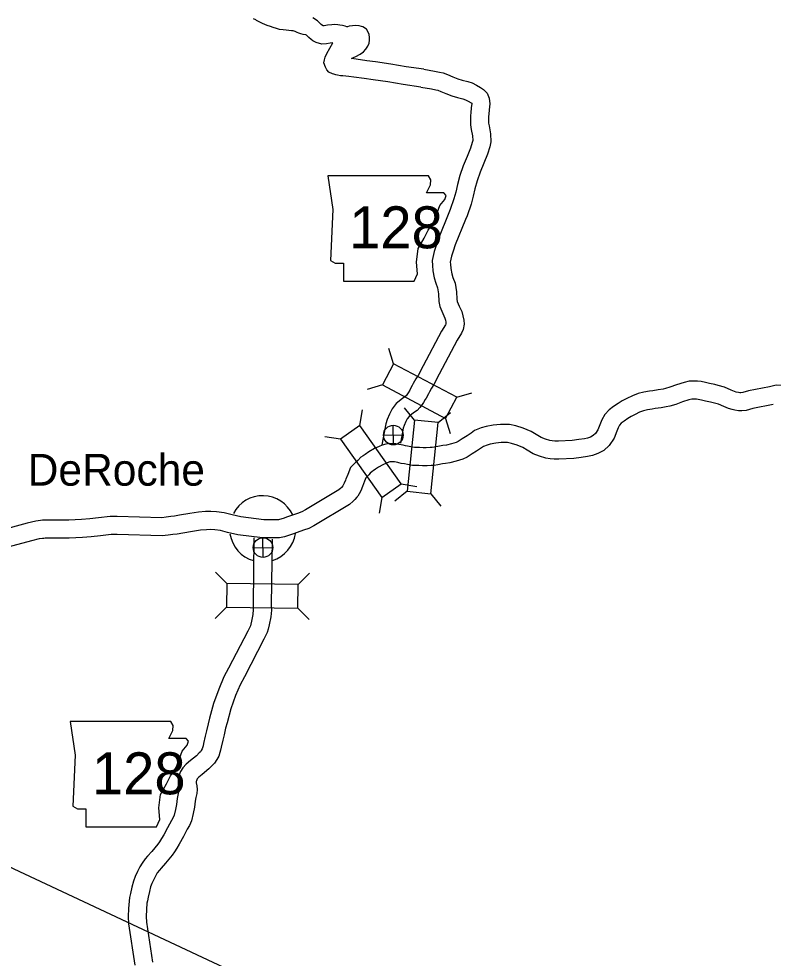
# Model space of a CAD drawing. Extents: x 1373862 to 1377080, y 1164775 to 1170415.
# Drawn here: x 1374284.4 to 1374409.6, y 1170151.1 to 1170307.2 of the extents above; entities that cross this region are included whole.
import ezdxf

# ---------------------------------------------------------------- set-up
doc = ezdxf.new("R2010")
doc.units = 0
doc.layers.add('1', color=7, linetype='Continuous')
doc.layers.add('Default', color=7, linetype='Continuous')

msp = doc.modelspace()

# ---------------------------------------------------------------- linework, layer by layer
at = {"layer": '1'}
msp.add_line((1374155.09, 1170226.04), (1374640.76, 1169998.76), dxfattribs=at)
at = {"layer": 'Default'}
for p, q in [((1374346.6, 1170249.86), (1374345.83, 1170252.38)), ((1374344.75, 1170246.36), (1374342.22, 1170245.59)), ((1374357.1, 1170244.29), (1374359.62, 1170245.06)), ((1374340.99, 1170239.6), (1374341.43, 1170242.21)), ((1374350.09, 1170240.49), (1374348.43, 1170242.54)), ((1374354.03, 1170240.08), (1374356.08, 1170241.75)), ((1374355.24, 1170240.79), (1374356.01, 1170238.27)), ((1374346.6, 1170236.39), (1374346.52, 1170239.64)), ((1374337.76, 1170237.31), (1374335.16, 1170237.75)), ((1374344.93, 1170237.98), (1374348.19, 1170238.05)), ((1374347.88, 1170229.93), (1374350.48, 1170229.49)), ((1374348.86, 1170228.68), (1374346.82, 1170227.01)), ((1374352.8, 1170228.27), (1374354.47, 1170226.22)), ((1374344.65, 1170227.63), (1374344.21, 1170225.03)), ((1374324.95, 1170217.69), (1374324.88, 1170220.95)), ((1374323.29, 1170219.28), (1374326.54, 1170219.36)), ((1374318.89, 1170213.36), (1374317.05, 1170215.25)), ((1374330.77, 1170213.21), (1374332.66, 1170215.06)), ((1374318.85, 1170209.4), (1374316.96, 1170207.55)), ((1374330.72, 1170209.25), (1374332.57, 1170207.36))]:
    msp.add_line(p, q, dxfattribs=at)
for points in [[(1374351.15, 1170295.83), (1374348.22, 1170296.24), (1374345.66, 1170296.7), (1374343.19, 1170297.05), (1374341.72, 1170297.25), (1374340, 1170297.51), (1374339.15, 1170297.61), (1374338.15, 1170297.72), (1374337.78, 1170297.73), (1374337.31, 1170297.8), (1374337, 1170297.86), (1374336.7, 1170297.96), (1374336.45, 1170298.02), (1374335.84, 1170298.33), (1374335.51, 1170298.72), (1374335.27, 1170299.14), (1374335.04, 1170299.85), (1374335.15, 1170300.38), (1374335.23, 1170300.78), (1374335.53, 1170301.42), (1374336.54, 1170303.19), (1374336.06, 1170303.13), (1374335.44, 1170303.02), (1374334.67, 1170302.96), (1374333.73, 1170303.24), (1374333.2, 1170303.53), (1374332.89, 1170303.76), (1374332.55, 1170304.05), (1374332.31, 1170304.29), (1374332.15, 1170304.44), (1374332.05, 1170304.5), (1374331.6, 1170304.57), (1374331.18, 1170304.68), (1374330.89, 1170304.77), (1374330.57, 1170304.93), (1374330.38, 1170305.03), (1374330.27, 1170305.07), (1374330.08, 1170305.13), (1374329.93, 1170305.16), (1374329.67, 1170305.19), (1374329.19, 1170305.23), (1374328.75, 1170305.31), (1374328.29, 1170305.35), (1374327.64, 1170305.43), (1374327.16, 1170305.55), (1374326.62, 1170305.74), (1374326.16, 1170305.88), (1374325.62, 1170306.06), (1374324.86, 1170306.39), (1374324.4, 1170306.6), (1374323.83, 1170306.91), (1374323.7, 1170307), (1374323.35, 1170307.18)], [(1374351.62, 1170298.79), (1374348.69, 1170299.21), (1374346.14, 1170299.66), (1374343.6, 1170300.03), (1374342.14, 1170300.22), (1374340.4, 1170300.49), (1374339.64, 1170300.57), (1374339.81, 1170300.67), (1374340.04, 1170300.83), (1374340.36, 1170300.94), (1374341.04, 1170301.3), (1374341.61, 1170301.71), (1374342.02, 1170302.13), (1374342.33, 1170302.65), (1374342.53, 1170303.13), (1374342.62, 1170303.65), (1374342.62, 1170304.1), (1374342.55, 1170304.56), (1374342.36, 1170304.96), (1374342.08, 1170305.44), (1374341.48, 1170305.83), (1374341.25, 1170305.88), (1374340.9, 1170306.02), (1374340.26, 1170306.08), (1374339.77, 1170306.03), (1374339.21, 1170305.93), (1374338.96, 1170305.86), (1374338.94, 1170305.86), (1374338.93, 1170305.86), (1374338.85, 1170305.87), (1374338.58, 1170305.95), (1374338.1, 1170306.06), (1374337.68, 1170306.11), (1374337.33, 1170306.16), (1374336.86, 1170306.21), (1374336.35, 1170306.19), (1374335.61, 1170306.1), (1374335.05, 1170306), (1374334.99, 1170305.99), (1374334.88, 1170306.02), (1374334.83, 1170306.05), (1374334.78, 1170306.09), (1374334.59, 1170306.26), (1374334.37, 1170306.47), (1374333.95, 1170306.86), (1374333.19, 1170307.32)], [(1374351.62, 1170298.79), (1374353.41, 1170298.48), (1374354.24, 1170298.33), (1374354.85, 1170298.18), (1374355.57, 1170297.91), (1374356.46, 1170297.53), (1374357.26, 1170297.2), (1374358.02, 1170296.99), (1374358.94, 1170296.75), (1374359.65, 1170296.52), (1374360.4, 1170296.17), (1374361.06, 1170295.78), (1374361.55, 1170295.45), (1374362.17, 1170294.82), (1374362.5, 1170294), (1374362.61, 1170293.07), (1374362.47, 1170292.08), (1374362.42, 1170291.35), (1374362.39, 1170290.95), (1374362.36, 1170290.37), (1374362.36, 1170289.85), (1374362.46, 1170289.37), (1374362.7, 1170288.09), (1374362.75, 1170286.72), (1374362.57, 1170285.89), (1374362.2, 1170284.67), (1374361.6, 1170283.17), (1374360.98, 1170281.68), (1374360.49, 1170280.24), (1374360.1, 1170278.91), (1374359.83, 1170277.7), (1374359.48, 1170276.38), (1374358.81, 1170274.44), (1374358.57, 1170273.83), (1374356.85, 1170269.6), (1374356.5, 1170268.59), (1374356.23, 1170267.73), (1374356.02, 1170266.77), (1374356.05, 1170266.43), (1374356.12, 1170265.72), (1374356.27, 1170264.82), (1374356.46, 1170264.19), (1374356.81, 1170263.25), (1374357.03, 1170261.81), (1374357.1, 1170260.58), (1374357.16, 1170260.22), (1374357.5, 1170259.42), (1374357.91, 1170258.53), (1374358.13, 1170257.85), (1374358.28, 1170257.13), (1374358.3, 1170256.45), (1374358.15, 1170255.55), (1374357.87, 1170254.93), (1374357.16, 1170253.79), (1374354.18, 1170248.12), (1374353.27, 1170246.44), (1374352.9, 1170245.82), (1374352.54, 1170245.19), (1374352.39, 1170244.88), (1374351.99, 1170244.14), (1374351.87, 1170243.94), (1374351.58, 1170243.44), (1374351.34, 1170243.09), (1374350.95, 1170242.58), (1374350.5, 1170242.12), (1374349.91, 1170241.7), (1374349.17, 1170241.12), (1374348.87, 1170240.74), (1374348.64, 1170240.28), (1374348.37, 1170239.6), (1374348.22, 1170239.14), (1374347.74, 1170236.65)], [(1374351.15, 1170295.83), (1374352.9, 1170295.52), (1374353.63, 1170295.4), (1374353.95, 1170295.32), (1374354.46, 1170295.12), (1374355.3, 1170294.77), (1374356.27, 1170294.36), (1374357.24, 1170294.09), (1374358.11, 1170293.86), (1374358.55, 1170293.72), (1374359.01, 1170293.51), (1374359.47, 1170293.24), (1374359.58, 1170293.17), (1374359.59, 1170293.1), (1374359.48, 1170292.39), (1374359.43, 1170291.58), (1374359.39, 1170291.14), (1374359.36, 1170290.43), (1374359.36, 1170289.56), (1374359.51, 1170288.79), (1374359.71, 1170287.76), (1374359.74, 1170286.98), (1374359.67, 1170286.65), (1374359.37, 1170285.67), (1374358.82, 1170284.31), (1374358.17, 1170282.73), (1374357.63, 1170281.15), (1374357.19, 1170279.65), (1374356.92, 1170278.4), (1374356.61, 1170277.25), (1374356, 1170275.48), (1374355.79, 1170274.94), (1374354.04, 1170270.66), (1374353.65, 1170269.53), (1374353.32, 1170268.49), (1374353.01, 1170267), (1374353.05, 1170266.2), (1374353.14, 1170265.33), (1374353.34, 1170264.13), (1374353.62, 1170263.23), (1374353.89, 1170262.5), (1374354.04, 1170261.51), (1374354.11, 1170260.22), (1374354.27, 1170259.36), (1374354.76, 1170258.21), (1374355.11, 1170257.44), (1374355.23, 1170257.09), (1374355.29, 1170256.78), (1374355.29, 1170256.65), (1374355.26, 1170256.42), (1374355.22, 1170256.34), (1374354.56, 1170255.29), (1374351.53, 1170249.53), (1374350.66, 1170247.93), (1374350.3, 1170247.34), (1374349.88, 1170246.59), (1374349.71, 1170246.25), (1374349.38, 1170245.62), (1374349.29, 1170245.46), (1374349.05, 1170245.05), (1374348.91, 1170244.86), (1374348.68, 1170244.55), (1374348.55, 1170244.42), (1374348.11, 1170244.1), (1374347.04, 1170243.25), (1374346.34, 1170242.38), (1374345.9, 1170241.51), (1374345.55, 1170240.62), (1374345.31, 1170239.9), (1374344.64, 1170236.42)], [(1374409.05, 1170246.05), (1374405.54, 1170245.36), (1374404.63, 1170245.08), (1374404.29, 1170245.06), (1374404.09, 1170245.05), (1374403.89, 1170245.09), (1374403.52, 1170245.16), (1374403.22, 1170245.24), (1374402.64, 1170245.5), (1374401.56, 1170245.96), (1374400.49, 1170246.27), (1374399.94, 1170246.41), (1374399.08, 1170246.6), (1374398.39, 1170246.76), (1374397.71, 1170246.91), (1374397.1, 1170246.99), (1374396.46, 1170246.99), (1374395.69, 1170246.95), (1374394.88, 1170246.75), (1374393.6, 1170246.38), (1374392.48, 1170245.95), (1374391.78, 1170245.73), (1374391.39, 1170245.67), (1374390.56, 1170245.52), (1374389.64, 1170245.38), (1374389.13, 1170245.31), (1374388.17, 1170245.15), (1374387.21, 1170244.93), (1374386.26, 1170244.56), (1374385.35, 1170244.12), (1374384.54, 1170243.68), (1374383.89, 1170243.27), (1374383.14, 1170242.77), (1374382.38, 1170242.2), (1374381.7, 1170241.44), (1374381.19, 1170240.56), (1374380.86, 1170239.73), (1374380.53, 1170238.86), (1374380.12, 1170238.25), (1374379.77, 1170237.93), (1374379.29, 1170237.68), (1374378.82, 1170237.5), (1374378.33, 1170237.4), (1374377.37, 1170237.28), (1374376.25, 1170237.12), (1374374, 1170237.02), (1374373.39, 1170237.03), (1374372.93, 1170237.06), (1374372.56, 1170237.12), (1374371.85, 1170237.33), (1374371.12, 1170237.62), (1374370.3, 1170238.11), (1374369.46, 1170238.61), (1374368.13, 1170239.17), (1374366.88, 1170239.55), (1374365.86, 1170239.75), (1374364.34, 1170239.78), (1374363.15, 1170239.64), (1374361.98, 1170239.44), (1374361.17, 1170239.21), (1374360.04, 1170238.77), (1374359.49, 1170238.33), (1374358.82, 1170237.91), (1374358, 1170237.41), (1374357.31, 1170236.95), (1374357.02, 1170236.8), (1374356.24, 1170236.56), (1374355.38, 1170236.36), (1374354.78, 1170236.27), (1374354.23, 1170236.19), (1374353.34, 1170236.03), (1374353, 1170235.95), (1374352.7, 1170235.95), (1374352, 1170235.89), (1374351.52, 1170235.88), (1374350.92, 1170235.94), (1374350.41, 1170235.94), (1374350.1, 1170235.95), (1374349.44, 1170236.08), (1374348.94, 1170236.16), (1374348.57, 1170236.24), (1374348.22, 1170236.34), (1374347.84, 1170236.42), (1374347.47, 1170236.47), (1374347.26, 1170236.51), (1374346.95, 1170236.56), (1374345.85, 1170236.59), (1374345.31, 1170236.53), (1374344.72, 1170236.33), (1374344.19, 1170236.09), (1374343.46, 1170235.77), (1374342.49, 1170235.22), (1374341.86, 1170234.78), (1374341.56, 1170234.56), (1374341.18, 1170234.33), (1374340.64, 1170233.8), (1374340.35, 1170233.51), (1374340.06, 1170233.22), (1374339.43, 1170232.61), (1374339, 1170231.47), (1374338.64, 1170230.57)], [(1374424.98, 1170242.16), (1374424.07, 1170242.59), (1374423.14, 1170242.91), (1374421.91, 1170243.35), (1374420.93, 1170243.7), (1374420.41, 1170243.96), (1374419.75, 1170244.38), (1374419.06, 1170244.79), (1374418.53, 1170245.02), (1374417.6, 1170245.46), (1374416.75, 1170245.81), (1374415.54, 1170246.12), (1374414.33, 1170246.27), (1374413.4, 1170246.26), (1374412.61, 1170246.22), (1374411.69, 1170246.24), (1374410.96, 1170246.27), (1374410.16, 1170246.29), (1374409.02, 1170246.04)], [(1374409.63, 1170243.1), (1374406.26, 1170242.44), (1374405.14, 1170242.1), (1374404.46, 1170242.07), (1374403.89, 1170242.03), (1374403.3, 1170242.15), (1374402.82, 1170242.24), (1374402.21, 1170242.41), (1374401.45, 1170242.75), (1374400.55, 1170243.13), (1374399.69, 1170243.38), (1374399.26, 1170243.49), (1374398.42, 1170243.67), (1374397.72, 1170243.83), (1374397.19, 1170243.95), (1374396.9, 1170243.99), (1374396.54, 1170243.99), (1374396.14, 1170243.97), (1374395.65, 1170243.85), (1374394.56, 1170243.54), (1374393.47, 1170243.11), (1374392.46, 1170242.8), (1374391.88, 1170242.71), (1374391.05, 1170242.56), (1374390.06, 1170242.41), (1374389.57, 1170242.34), (1374388.76, 1170242.21), (1374388.1, 1170242.05), (1374387.46, 1170241.81), (1374386.72, 1170241.45), (1374386.06, 1170241.09), (1374385.52, 1170240.75), (1374384.88, 1170240.32), (1374384.41, 1170239.98), (1374384.14, 1170239.67), (1374383.89, 1170239.24), (1374383.66, 1170238.65), (1374383.22, 1170237.48), (1374382.41, 1170236.28), (1374381.51, 1170235.45), (1374380.52, 1170234.94), (1374379.66, 1170234.61), (1374378.82, 1170234.44), (1374377.76, 1170234.3), (1374376.53, 1170234.13), (1374374.05, 1170234.02), (1374373.26, 1170234.03), (1374372.6, 1170234.07), (1374371.89, 1170234.19), (1374370.86, 1170234.5), (1374369.8, 1170234.91), (1374368.76, 1170235.53), (1374368.09, 1170235.93), (1374367.11, 1170236.35), (1374366.16, 1170236.63), (1374365.53, 1170236.76), (1374364.49, 1170236.78), (1374363.59, 1170236.67), (1374362.64, 1170236.51), (1374362.12, 1170236.36), (1374361.55, 1170236.14), (1374361.22, 1170235.88), (1374360.4, 1170235.36), (1374359.63, 1170234.89), (1374358.81, 1170234.34), (1374358.13, 1170234.01), (1374357.02, 1170233.66), (1374355.95, 1170233.42), (1374355.23, 1170233.3), (1374354.7, 1170233.23), (1374353.93, 1170233.09), (1374353.34, 1170232.96), (1374352.84, 1170232.95), (1374352.16, 1170232.9), (1374351.41, 1170232.88), (1374350.77, 1170232.94), (1374350.38, 1170232.94), (1374349.77, 1170232.96), (1374348.91, 1170233.12), (1374348.39, 1170233.21), (1374347.84, 1170233.32), (1374347.48, 1170233.43), (1374347.31, 1170233.47), (1374347.02, 1170233.51), (1374346.76, 1170233.55), (1374346.64, 1170233.57), (1374345.99, 1170233.59), (1374345.97, 1170233.58), (1374345.82, 1170233.54), (1374345.42, 1170233.35), (1374344.8, 1170233.08), (1374344.1, 1170232.69), (1374343.61, 1170232.34), (1374343.22, 1170232.05), (1374343.02, 1170231.94), (1374342.74, 1170231.66), (1374342.47, 1170231.4), (1374342.17, 1170231.09), (1374342, 1170230.92), (1374341.79, 1170230.38), (1374341.42, 1170229.45)], [(1374338.62, 1170230.54), (1374338.42, 1170230), (1374338.3, 1170229.79), (1374338.18, 1170229.6), (1374338.16, 1170229.58), (1374337.94, 1170229.3), (1374337.86, 1170229.22), (1374337.52, 1170228.92), (1374331.95, 1170225.57), (1374331.36, 1170225.28), (1374330.62, 1170225.01), (1374328.98, 1170224.42), (1374328.24, 1170224.17), (1374327.67, 1170224), (1374327.48, 1170223.95), (1374327.37, 1170223.93), (1374325.04, 1170223.94)], [(1374341.43, 1170229.48), (1374341.14, 1170228.73), (1374340.89, 1170228.28), (1374340.65, 1170227.89), (1374340.51, 1170227.71), (1374340.19, 1170227.3), (1374339.91, 1170227.02), (1374339.28, 1170226.48), (1374333.38, 1170222.93), (1374332.53, 1170222.52), (1374331.65, 1170222.19), (1374329.96, 1170221.58), (1374329.13, 1170221.31), (1374328.51, 1170221.13), (1374328.19, 1170221.03), (1374327.66, 1170220.93), (1374324.85, 1170220.94)], [(1374325.04, 1170223.94), (1374321.26, 1170224.41), (1374319.77, 1170224.76), (1374318.46, 1170225.12), (1374317.19, 1170225.27), (1374316.26, 1170225.33), (1374315.36, 1170225.29), (1374314.2, 1170225.2), (1374312.74, 1170224.98), (1374311.04, 1170224.69), (1374310.21, 1170224.52), (1374309.6, 1170224.46), (1374308.84, 1170224.35), (1374308.09, 1170224.29), (1374300.7, 1170224.51), (1374299.51, 1170224.49), (1374297.58, 1170224.26), (1374296.14, 1170224.11), (1374294.77, 1170224.01), (1374292.66, 1170223.9), (1374291.94, 1170223.89), (1374290.89, 1170223.88), (1374289.96, 1170223.86), (1374289.17, 1170223.87), (1374288.68, 1170223.86), (1374288.32, 1170223.85), (1374287.96, 1170223.82), (1374287.19, 1170223.71), (1374285.75, 1170223.37), (1374281.03, 1170222.1)], [(1374324.85, 1170220.94), (1374320.73, 1170221.45), (1374319.02, 1170221.85), (1374317.88, 1170222.17), (1374316.92, 1170222.28), (1374316.23, 1170222.32), (1374315.54, 1170222.29), (1374314.54, 1170222.22), (1374313.22, 1170222.02), (1374311.59, 1170221.74), (1374310.66, 1170221.55), (1374309.95, 1170221.48), (1374309.16, 1170221.37), (1374308.17, 1170221.29), (1374300.68, 1170221.51), (1374299.72, 1170221.5), (1374297.92, 1170221.28), (1374296.4, 1170221.12), (1374294.96, 1170221.01), (1374292.75, 1170220.9), (1374291.96, 1170220.89), (1374290.93, 1170220.88), (1374289.99, 1170220.86), (1374289.18, 1170220.87), (1374288.76, 1170220.86), (1374288.5, 1170220.85), (1374288.3, 1170220.84), (1374287.75, 1170220.76), (1374286.48, 1170220.46), (1374281.73, 1170219.18)], [(1374323.42, 1170220.93), (1374323.29, 1170209.81), (1374323.31, 1170209.02), (1374323.24, 1170208.23), (1374323.02, 1170207.12), (1374322.9, 1170206.57), (1374322.82, 1170206.34), (1374322.39, 1170205.45), (1374319.16, 1170199.26), (1374318.41, 1170197.82), (1374317.57, 1170195.81), (1374316.71, 1170193.44), (1374316.04, 1170191), (1374315.79, 1170190.01), (1374315.52, 1170188.89), (1374315.32, 1170187.98), (1374315.04, 1170186.76), (1374314.96, 1170186.37), (1374314.9, 1170186.19), (1374314.79, 1170185.86), (1374314.66, 1170185.61), (1374314.54, 1170185.41), (1374314.31, 1170185.2), (1374313.87, 1170184.74), (1374312.9, 1170183.94), (1374312.16, 1170183.35), (1374311.62, 1170182.7), (1374311.23, 1170182.14), (1374310.96, 1170181.37), (1374310.81, 1170180.69), (1374310.85, 1170179.95), (1374310.94, 1170179.34), (1374310.97, 1170179.08), (1374310.96, 1170178.98), (1374310.82, 1170178.45), (1374310.68, 1170177.62), (1374310.56, 1170176.66), (1374310.4, 1170175.8), (1374310.17, 1170174.86), (1374310.01, 1170174.49), (1374309.72, 1170173.96), (1374309.05, 1170172.74), (1374308.42, 1170171.58), (1374308.04, 1170170.96), (1374307.72, 1170170.43), (1374307.45, 1170170.07), (1374306.93, 1170169.43), (1374306.45, 1170168.83), (1374305.72, 1170168.05), (1374305.34, 1170167.59), (1374304.83, 1170166.89), (1374304.48, 1170166.26), (1374304.08, 1170165.48), (1374303.71, 1170164.66), (1374303.39, 1170163.88), (1374303.14, 1170162.91), (1374302.9, 1170161.85), (1374302.76, 1170161.16), (1374302.67, 1170160.56), (1374302.58, 1170159.36), (1374302.53, 1170158.01), (1374302.6, 1170156.79), (1374303.61, 1170149.92)], [(1374326.42, 1170220.72), (1374326.29, 1170209.82), (1374326.31, 1170208.93), (1374326.22, 1170207.81), (1374325.96, 1170206.5), (1374325.79, 1170205.76), (1374325.6, 1170205.19), (1374325.07, 1170204.1), (1374321.82, 1170197.87), (1374321.13, 1170196.54), (1374320.36, 1170194.72), (1374319.57, 1170192.54), (1374318.94, 1170190.22), (1374318.7, 1170189.29), (1374318.45, 1170188.22), (1374318.25, 1170187.32), (1374317.97, 1170186.14), (1374317.88, 1170185.64), (1374317.76, 1170185.26), (1374317.56, 1170184.67), (1374317.26, 1170184.11), (1374316.87, 1170183.49), (1374316.42, 1170183.07), (1374315.91, 1170182.54), (1374314.79, 1170181.62), (1374314.28, 1170181.2), (1374314.01, 1170180.88), (1374313.92, 1170180.76), (1374313.85, 1170180.54), (1374313.83, 1170180.44), (1374313.84, 1170180.26), (1374313.91, 1170179.75), (1374313.99, 1170179.13), (1374313.93, 1170178.45), (1374313.76, 1170177.81), (1374313.65, 1170177.18), (1374313.53, 1170176.2), (1374313.33, 1170175.16), (1374313.02, 1170173.91), (1374312.71, 1170173.17), (1374312.34, 1170172.51), (1374311.69, 1170171.32), (1374311.02, 1170170.07), (1374310.6, 1170169.39), (1374310.21, 1170168.76), (1374309.83, 1170168.23), (1374309.26, 1170167.54), (1374308.72, 1170166.87), (1374307.98, 1170166.07), (1374307.71, 1170165.75), (1374307.36, 1170165.26), (1374307.12, 1170164.84), (1374306.79, 1170164.19), (1374306.47, 1170163.49), (1374306.25, 1170162.93), (1374306.06, 1170162.2), (1374305.83, 1170161.22), (1374305.71, 1170160.63), (1374305.65, 1170160.23), (1374305.58, 1170159.2), (1374305.53, 1170158.03), (1374305.59, 1170157.09), (1374306.57, 1170150.41)]]:
    msp.add_lwpolyline(points, dxfattribs=at)
for points in [[(1374335.69, 1170281.09), (1374336.52, 1170275.5), (1374336.15, 1170267.04), (1374336.9, 1170266.57), (1374338.29, 1170266.57), (1374338.29, 1170263.59), (1374350.02, 1170263.59), (1374350.57, 1170264.8), (1374350.39, 1170266.76), (1374350.67, 1170268.99), (1374351.69, 1170270.76), (1374352.34, 1170272.06), (1374353.27, 1170273.46), (1374353.83, 1170274.94), (1374354.3, 1170276.15), (1374355.13, 1170277.18), (1374355.32, 1170277.83), (1374354.95, 1170278.29), (1374352.06, 1170278.29), (1374352.71, 1170279.6), (1374352.81, 1170280.43), (1374352.42, 1170281.08)], [(1374357.1, 1170244.29), (1374346.6, 1170249.86), (1374344.75, 1170246.36), (1374355.24, 1170240.79)], [(1374352.8, 1170228.27), (1374354.03, 1170240.08), (1374350.09, 1170240.49), (1374348.86, 1170228.68)], [(1374347.88, 1170229.93), (1374340.99, 1170239.6), (1374337.76, 1170237.31), (1374344.65, 1170227.63)], [(1374330.77, 1170213.21), (1374318.89, 1170213.36), (1374318.85, 1170209.4), (1374330.72, 1170209.25)], [(1374292.9, 1170190.41), (1374293.73, 1170184.82), (1374293.36, 1170176.36), (1374294.1, 1170175.89), (1374295.5, 1170175.89), (1374295.5, 1170172.91), (1374307.22, 1170172.91), (1374307.78, 1170174.12), (1374307.6, 1170176.08), (1374307.88, 1170178.31), (1374308.9, 1170180.08), (1374309.55, 1170181.38), (1374310.48, 1170182.78), (1374311.04, 1170184.26), (1374311.51, 1170185.47), (1374312.34, 1170186.5), (1374312.53, 1170187.15), (1374312.16, 1170187.61), (1374309.27, 1170187.61), (1374309.92, 1170188.92), (1374310.02, 1170189.75), (1374309.63, 1170190.4)]]:
    msp.add_lwpolyline(points, close=True, dxfattribs=at)
for centre in [(1374346.56, 1170238.01), (1374324.92, 1170219.32)]:
    msp.add_circle(centre, 1.63, dxfattribs=at)
for start, end in [(24.975, 152.2052), (188.8913, 254.0641), (287.1876, 351.9284)]:
    msp.add_arc((1374324.86, 1170222.44), 5.5, start, end, dxfattribs=at)

# ---------------------------------------------------------------- texts
for s, height, p in [('128', 6.97, (1374339.22, 1170269.05)), ('DeRoche', 5.28, (1374285.84, 1170229.61)), ('128', 6.97, (1374296.51, 1170178.33))]:
    msp.add_text(s, height=height, dxfattribs=at).set_placement(p)

doc.saveas('drawing.dxf')
